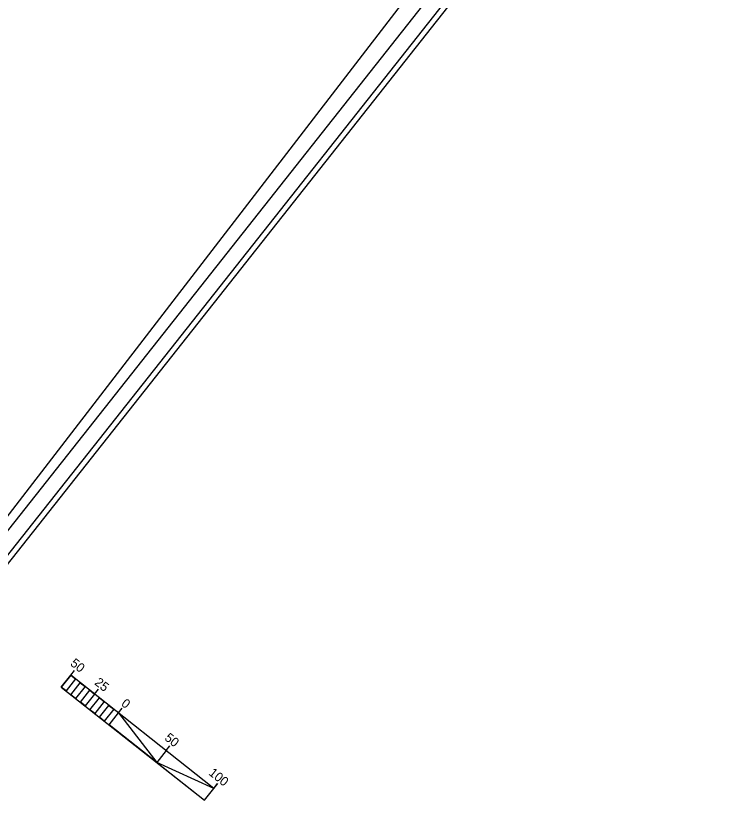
# Model space of a CAD drawing. Extents: x 556999 to 559002, y 505273 to 507273.
# Drawn here: x 558407 to 559002, y 505273 to 505917 of the extents above; entities that cross this region are included whole.
import ezdxf

# ---------------------------------------------------------------- set-up
doc = ezdxf.new("R2010")
doc.units = 0
for name, color, linetype in [('Sheet Border Standard 30in CELL', 7, 'Continuous'), ('Sheet Clip Boundary CELL', 7, 'Continuous'), ('Sheet Data Field CELL', 7, 'Continuous'), ('Sheet Plot Border Inside CELL', 7, 'Continuous'), ('Sheet Plot Border Outside CELL', 7, 'Continuous'), ('Sheet Title CELL', 7, 'Continuous')]:
    doc.layers.add(name, color=color, linetype=linetype)

msp = doc.modelspace()

# ---------------------------------------------------------------- linework, layer by layer
at = {"layer": 'Sheet Border Standard 30in CELL'}
msp.add_lwpolyline([(558973.57, 506219.71), (557796.95, 507150.06), (557145.7, 506326.43), (558322.33, 505396.07)], close=True, dxfattribs=at)
at = {"layer": 'Sheet Clip Boundary CELL'}
msp.add_lwpolyline([(558069.07, 506542.35), (558502.21, 506199.86), (558564.29, 506127.01), (558761.1, 505975.77), (558323.19, 505407.07), (558300.81, 505488.36), (558208.66, 505547.92), (558125.54, 505588.21), (558099.51, 505637.12), (558051.88, 505660.91), (558034.88, 505701.52), (557812.51, 505806.82), (557792.13, 505912.23), (557814.64, 506029.85), (557725.94, 506096.17), (557744.19, 506089.08), (557749.43, 506157.45), (557759.11, 506179.01), (557817.46, 506256.09), (557969.3, 506353.49), (557953.99, 506367.89), (557981.23, 506420.97), (558000.13, 506451.2)], close=True, dxfattribs=at)
at = {"layer": 'Sheet Data Field CELL'}
for p, q in [((558451.92, 505375.47), (558455.02, 505379.38)), ((558471.53, 505359.96), (558474.63, 505363.88)), ((558530.37, 505313.45), (558533.46, 505317.37)), ((558569.59, 505282.44), (558572.7, 505286.37))]:
    msp.add_line(p, q, dxfattribs=at)
at = {"layer": 'Sheet Plot Border Inside CELL'}
msp.add_lwpolyline([(558984.96, 506213.96), (557677.73, 507247.58), (557023.32, 506419.94), (558330.55, 505386.32)], close=True, dxfattribs=at)
at = {"layer": 'Sheet Plot Border Outside CELL'}
msp.add_lwpolyline([(559002.42, 506228.78), (557681.46, 507273.25), (556999.2, 506410.4), (558320.16, 505365.92)], close=True, dxfattribs=at)
at = {"layer": 'Sheet Title CELL'}
for p, q in [((558451.91, 505375.47), (558444.15, 505365.66)), ((558451.91, 505375.47), (558455, 505379.38)), ((558569.58, 505282.44), (558451.91, 505375.47)), ((558444.15, 505365.66), (558561.82, 505272.63)), ((558471.51, 505359.95), (558474.62, 505363.89)), ((558479.36, 505353.76), (558471.61, 505343.96)), ((558491.12, 505344.45), (558494.22, 505348.37)), ((558530.35, 505313.45), (558533.45, 505317.36)), ((558530.35, 505313.45), (558522.6, 505303.65)), ((558569.58, 505282.44), (558572.68, 505286.37)), ((558561.82, 505272.63), (558569.58, 505282.44))]:
    msp.add_line(p, q, dxfattribs=at)
for points in [[(558451.91, 505375.47), (558455.83, 505372.37), (558448.08, 505362.56), (558444.15, 505365.66)], [(558459.75, 505369.27), (558463.67, 505366.16), (558455.91, 505356.35), (558452, 505359.44)], [(558467.59, 505363.06), (558471.51, 505359.95), (558463.77, 505350.16), (558459.84, 505353.26)], [(558475.43, 505356.85), (558479.36, 505353.76), (558471.61, 505343.96), (558467.69, 505347.06)], [(558483.29, 505350.66), (558487.21, 505347.56), (558479.45, 505337.75), (558475.53, 505340.86)], [(558491.12, 505344.45), (558522.6, 505303.65), (558483.37, 505334.64)], [(558569.58, 505282.44), (558522.6, 505303.65), (558561.82, 505272.63)]]:
    msp.add_lwpolyline(points, close=True, dxfattribs=at)

# ---------------------------------------------------------------- texts
for s, p in [('50', (558450.95, 505384.05)), ('25', (558470.83, 505368.33)), ('0', (558492.78, 505350.98)), ('50', (558528.43, 505322.8)), ('100', (558564.78, 505294.06))]:
    msp.add_text(s, height=7.5, rotation=321.67144, dxfattribs=at).set_placement(p)

doc.saveas('drawing.dxf')
